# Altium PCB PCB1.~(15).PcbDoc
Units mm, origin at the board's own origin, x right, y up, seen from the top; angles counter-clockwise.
Board outline 145.29 x 144.91 mm, 2 copper layers (Top Layer, Bottom Layer); 48 components, 44 nets, 249 pads, 0 vias.
Unrouted connection lines stored in the file: 182.
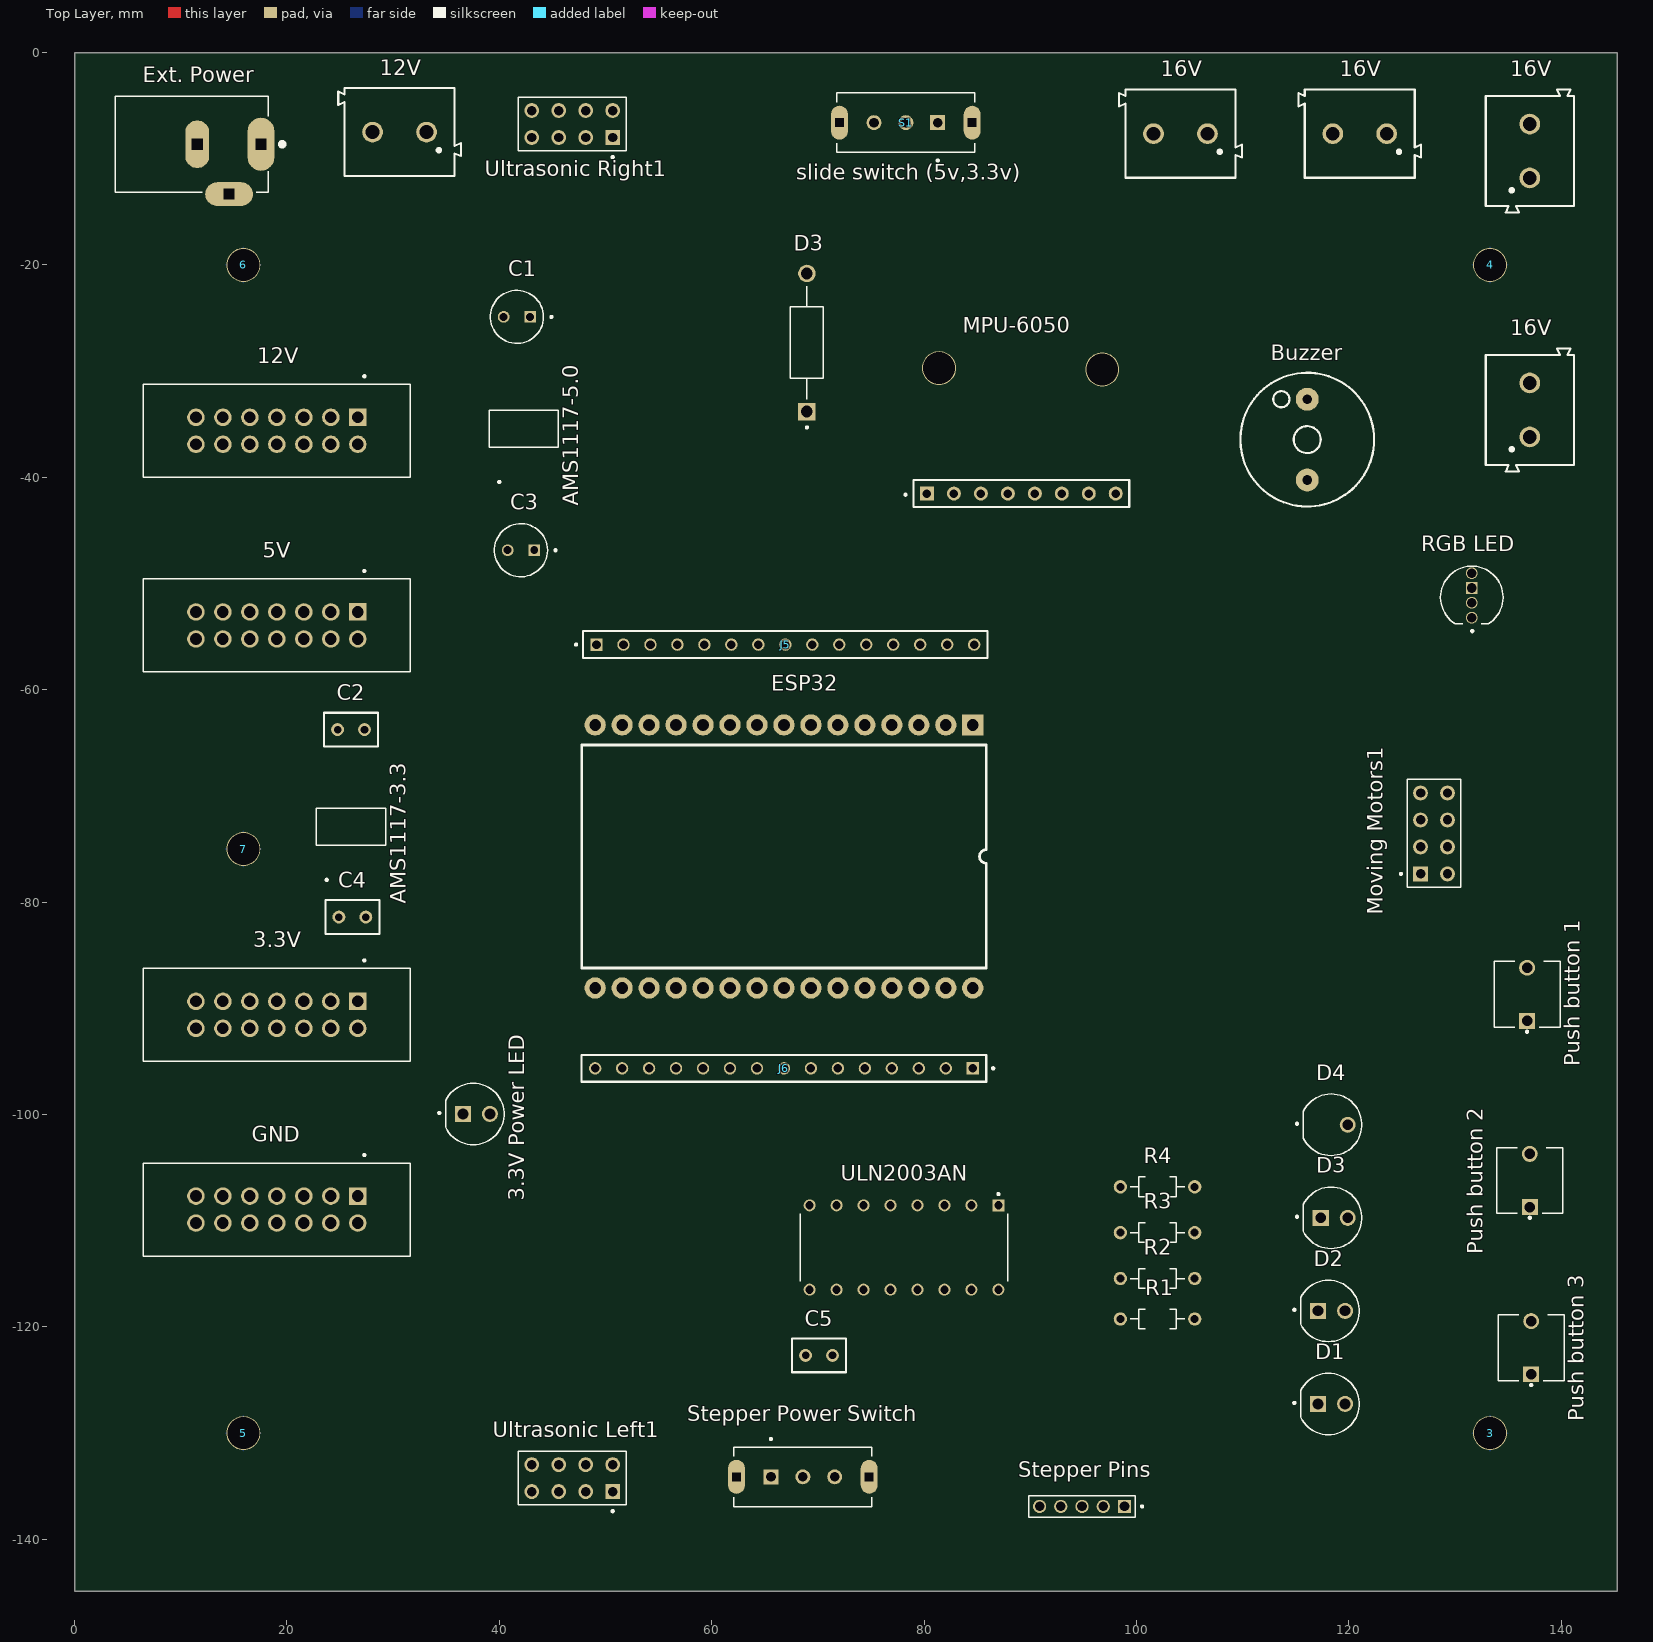
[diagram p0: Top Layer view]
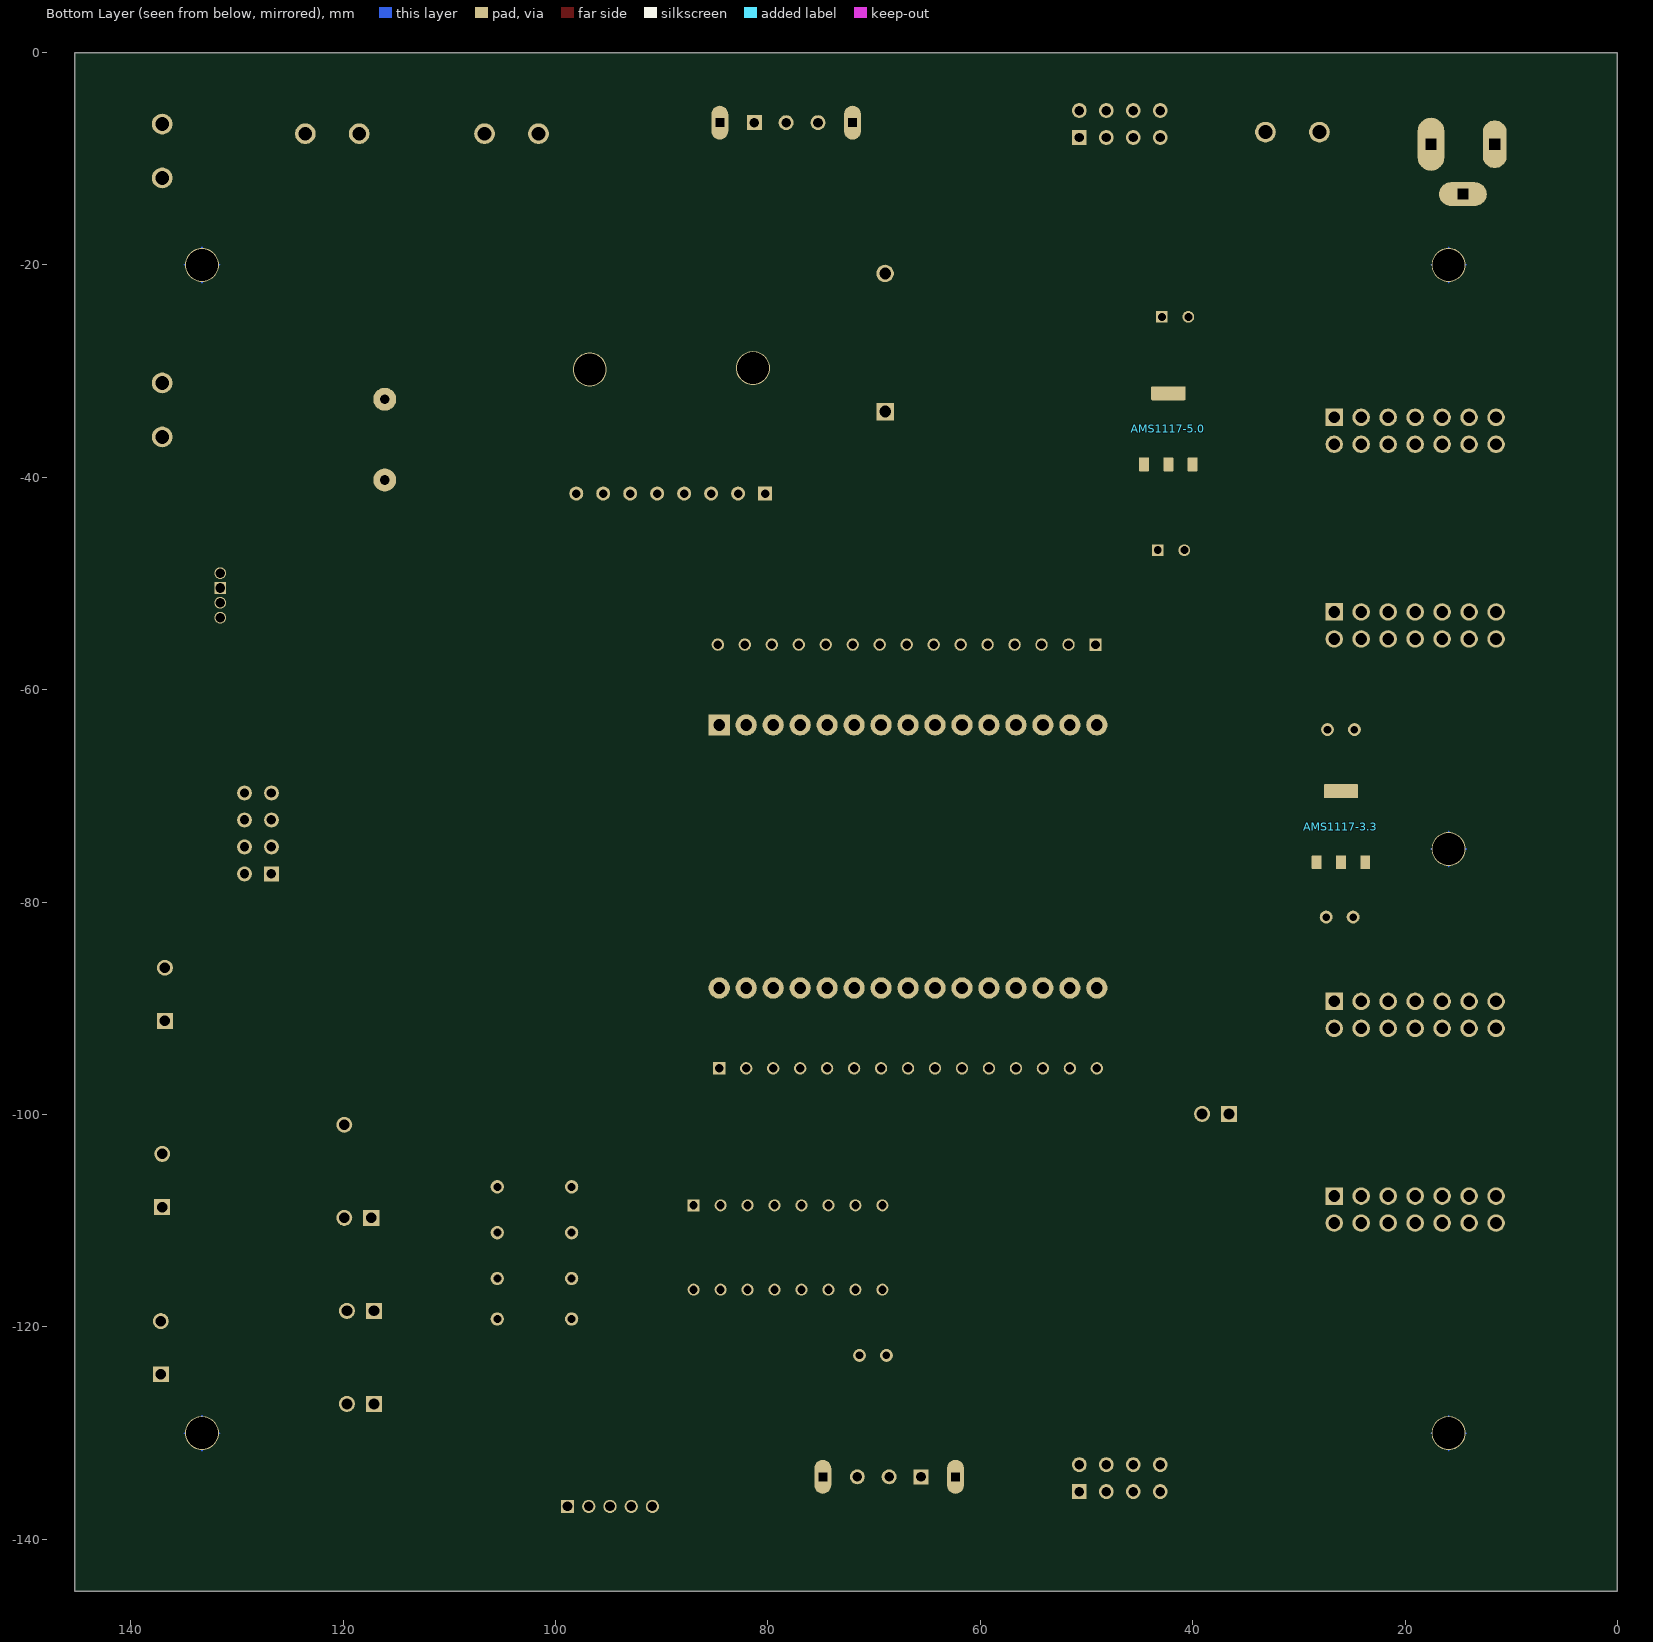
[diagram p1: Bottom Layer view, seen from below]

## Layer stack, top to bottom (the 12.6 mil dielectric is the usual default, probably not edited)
Top Solder: solder mask 0.0102, Solder Resist, Dk 3.5
Top Layer: signal copper 0.0356
Dielectric 1: dielectric 0.32, FR-4, Dk 4.8
Bottom Layer: signal copper 0.0356
Bottom Solder: solder mask 0.0102, Solder Resist, Dk 3.5

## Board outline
0,-144.907 145.288,-144.907 145.288,0 0,0

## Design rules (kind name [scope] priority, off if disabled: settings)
Clearance [All] p1: gap=0.254 ignorepadtopadclearanceinfootprint=FALSE except(0: Arc-Hole Track-Hole SMDPad-Hole THPad-Hole Via-Hole Fill-Hole Poly-Hole Region-Hole Text-Hole)
PolygonConnect [All] p1: connectstyle=Relief reliefconductorwidth=0.254 reliefentries=4 polygonreliefangle="90 Angle" airgapwidth=0.254
RoutingLayers [All] p1: top layer_v5=FALSE bottom layer_v5=TRUE
RoutingVias [All] p1: holewidth=0.711 width=1.27 viastyle="Through Hole" minholewidth=0.711 minwidth=1.27 maxholewidth=0.711 maxwidth=1.27
SolderMaskExpansion [All] p1: expansion=0.102 istentingtop=FALSE
Width [All] p1: maxlimit=0.5 minlimit=0.254 preferedwidth=0.5
29 further rules are at their usual default settings.

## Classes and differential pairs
component class Sheet1: 3 3.3V "3.3V Power LED" 4 5 5V 6 7 12V 16V AMS1117-3.3 AMS1117-5.0 Buzzer C1 C2 C3 C4 C5 D1 D2 D3 D4 ESP32 "Ext. Power" GND J5 J6 "Moving motors" "Moving Motors1" MPU-6050 "Push button 1" "Push button 2" "Push button 3" R1 R2 R3 R4 "RGB LED" S1 "Stepper Pins" "Stepper Power Switch" ULN2003AN "Ultrasonic Left1" "Ultrasonic Right1"

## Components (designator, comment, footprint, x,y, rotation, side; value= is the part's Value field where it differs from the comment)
3 "Mounting Hole" PCBComponent_1 133.288,-130 r90 top
3.3V "3.3v pin headers block" AMPHENOL_52601-S14-4LF 19.05,-90.616 r180 top
"3.3V Power LED" "LED 5mm" "LED 5mm"#1 37.846,-99.949 r0 top
4 "Mounting Hole" PCBComponent_1 133.288,-20 r90 top
5 "Mounting Hole" PCBComponent_1 15.9,-130 r90 top
5V "5v pin headers block" AMPHENOL_52601-S14-4LF 19.05,-53.949 r180 top
6 "Mounting Hole" PCBComponent_1 15.9,-20 r90 top
7 "Mounting Hole" PCBComponent_1 15.9,-75 r90 top
12V "12v pin headers block" AMPHENOL_52601-S14-4LF 19.05,-35.616 r180 top
12V "From Buck" 691213510002 30.607,-7.493 r180 top
16V "From Buck" 691213510002 137.033,-9.271 r90 top
16V "From Buck" 691213510002 137.033,-33.655 r90 top
16V "From Buck" 691213510002 121.02,-7.641 r180 top
16V "From Buck" 691213510002 104.14,-7.641 r180 top
AMS1117-3.3 "AMS1117-3.3" SOT229P700X180-4N 26.035,-72.898 r90 top
AMS1117-5.0 "AMS1117-5.0" SOT229P700X180-4N 42.291,-35.433 r90 top
Buzzer "WST-1205S" WST-1205S 116.078,-36.449 r90 top
C1 "CAP  33UF 50V RADIAL" "CAP  33UF 50V RADIAL" 41.656,-24.892 r180 top
C2 "Ceramic Capacitor 100nF" C320C 33.035,-56.754 r0 top
C3 "CAP  33UF 50V RADIAL" "CAP  33UF 50V RADIAL" 42.037,-46.863 r180 top
C4 "Ceramic Capacitor 100nF" C320C 33.162,-74.407 r0 top
C5 "Ceramic Capacitor 100nF" C320C 63.104,-129.682 r180 top
D1 "LED 5mm" "LED 5mm"#1 118.364,-127.254 r0 top
D2 "LED 5mm" "LED 5mm"#1 118.364,-118.491 r0 top
D3 "LED 5mm" "LED 5mm"#1 118.618,-109.728 r0 top
D3 "RL207" DIOAD1300W80L670D310 68.961,-27.305 r90 top
D4 "LED 5mm" "LED 5mm"#2 118.618,-100.965 r0 top
ESP32 "ESP32DEVKITV1" ESP32DEVKITV1 66.929,-75 r90 top
"Ext. Power" "DC Power Jack Female Socket" "DC Power Jack Female Socket" 17.557,-8.636 r180 top
GND "GND pin headers block" AMPHENOL_52601-S14-4LF 19.05,-108.949 r180 top
J5 "TS-115-T-A-1" SAMTEC_TS-115-T-A-1 66.929,-55.753 r0 top
J6 "TS-115-T-A-1" SAMTEC_TS-115-T-A-1 66.802,-95.649 r180 top
"Moving Motors1" "Pin header female block 8 pin" "Pin header female block 8 pin" 128.016,-73.533 r90 top (schematic designator "Moving motors1")
MPU-6050 "MPU-6050" MPU-6050 78.74,-43.053 r90 top
"Push button 1" "FSM8JRT" TE_FSM8JRT 136.779,-91.186 r90 top
"Push button 2" "FSM8JRT" TE_FSM8JRT 137.033,-108.712 r90 top
"Push button 3" "FSM8JRT" TE_FSM8JRT 137.16,-124.46 r90 top
R1 "Resistor" RESAD700W45L350D185 101.981,-119.253 r180 top
R2 "Resistor" RESAD700W45L350D185 101.981,-115.443 r180 top
R3 "Resistor" RESAD700W45L350D185 101.981,-111.125 r180 top
R4 "Resistor" RESAD700W45L350D185 101.981,-106.807 r180 top
"RGB LED" "common cathode" "LED RGB 5mm" 131.572,-51.308 r90 top
S1 "slide switch (5v,3.3v)" "Slide switch" 78.28,-6.604 r180 top
"Stepper Pins" "Pin hreader 5 pins" "Pin hreader 5 pins" 98.869,-136.906 r180 top
"Stepper Power Switch" "Slide switch" "Slide switch" 68.58,-134.112 r0 top
ULN2003AN "ULN2003AN" DIP794W45P254L1969H508Q16 78.105,-112.522 r270 top
"Ultrasonic Left1" "Pin header female block 8 pin" "Pin header female block 8 pin" 46.863,-134.239 r180 top
"Ultrasonic Right1" "Pin header female block 8 pin" "Pin header female block 8 pin" 46.863,-6.731 r180 top

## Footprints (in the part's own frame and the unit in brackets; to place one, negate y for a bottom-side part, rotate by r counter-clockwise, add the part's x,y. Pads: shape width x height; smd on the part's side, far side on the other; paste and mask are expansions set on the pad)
691213510002 [mm]
  round 1.95 hole 1.3: 1(-2.54,0) 2(2.54,0)
  silkscreen extent -5.78,-4.15 5.78,4.15, body extent -5.68,-3.94 5.68,4.16, height 10
AMPHENOL_52601-S14-4LF [mm]
  rect 1.65x1.65 hole 1.1: 1(-7.62,-1.27)
  round 1.65 hole 1.1: 2(-7.62,1.27) 3(-5.08,-1.27) 4(-5.08,1.27) 5(-2.54,-1.27) 6(-2.54,1.27) 7(0,-1.27) 8(0,1.27) 9(2.54,-1.27) 10(2.54,1.27) 11(5.08,-1.27) 12(5.08,1.27) 13(7.62,-1.27) 14(7.62,1.27)
  silkscreen extent -12.57,-5.23 12.57,4.38, body extent -12.57,-4.38 12.57,4.38, height 9.53
C320C [mm]
  round 1.21 hole 0.71: 1(-8.27,-7) 2(-5.73,-7)
  silkscreen extent -9.54,-8.59 -4.46,-5.41, body extent -9.53,-8.57 -4.45,-5.4, height 7.1
"CAP  33UF 50V RADIAL" [mm]
  round 1.1 hole 0.75: N(1.25,0)
  rect 1.1x1.1 hole 0.75: P(-1.25,0)
  silkscreen extent -3.35,-2.5 2.5,2.5, body extent -2.49,-2.5 2.5,2.5, height 11
"DC Power Jack Female Socket" [mm]
  oval 2.5x5 hole 1 square: 1(0,0)
  oval 2.25x4.5 hole 1 square: 2(6,0)
  oval 4.5x2.25 hole 1 square: 3(3,4.7)
  silkscreen extent -2.2,-4.5 13.7,4.5, body extent -0.7,-4.5 13.7,4.9, height 11
DIOAD1300W80L670D310 [mm]
  round 1.65 hole 1.1: A(6.5,0)
  rect 1.65x1.65 hole 1.1: C(-6.5,0)
  silkscreen extent -8.1,-1.55 5.32,1.55, body extent -6.9,-1.95 6.9,1.65, height 3.6
DIP794W45P254L1969H508Q16 [mm]
  rect 1.13x1.13 hole 0.78: 1(-3.97,8.89)
  round 1.13 hole 0.78: 2(-3.97,6.35) 3(-3.97,3.81) 4(-3.97,1.27) 5(-3.97,-1.27) 6(-3.97,-3.81) 7(-3.97,-6.35) 8(-3.97,-8.89) 9(3.97,-8.89) 10(3.97,-6.35) 11(3.97,-3.81) 12(3.97,-1.27) 13(3.97,1.27) 14(3.97,3.81) 15(3.97,6.35) 16(3.97,8.89)
  silkscreen extent -5.13,-9.77 3.18,9.77, body extent -3.95,-10.54 3.95,10.8, height 5.08
ESP32DEVKITV1 [mm]
  rect 2x2 hole 1.1: 1(11.684,-17.653)
  round 2 hole 1.1: 2(11.684,-15.113) 3(11.684,-12.573) 4(11.684,-10.033) 5(11.684,-7.493) 6(11.684,-4.953) 7(11.684,-2.413) 8(11.684,0.127) 9(11.684,2.667) 10(11.684,5.207) 11(11.684,7.747) 12(11.684,10.287) 13(11.684,12.827) 14(11.684,15.367) 15(11.684,17.907) 16(-13.086,17.907) 17(-13.086,15.367) 18(-13.086,12.827) 19(-13.086,10.287) 20(-13.086,7.747) 21(-13.086,5.207) 22(-13.086,2.667) 23(-13.086,0.127) 24(-13.086,-2.413) 25(-13.086,-4.953) 26(-13.086,-7.493) 27(-13.086,-10.033) 28(-13.086,-12.573) 29(-13.086,-15.113) 30(-13.086,-17.653)
  silkscreen extent -11.2,-18.92 9.79,19.18, body extent -15.13,-28.49 13.86,24.48, height 8.36
"LED 5mm"#1 [mm]
  round 1.508 hole 1: A(1.27,0)
  rect 1.508x1.508 hole 1: C(-1.27,0)
  silkscreen extent -3.6,-2.9 2.6,2.9, body extent -2.88,-2.9 2.51,2.9, height 12.1
"LED 5mm"#2 [mm]
  round 1.508 hole 1: A(1.27,0)
  rect 1.508x1.508 on Top Overlay: C(-1.27,0)
  silkscreen extent -3.6,-2.9 2.6,2.9, body extent -2.88,-2.9 2.51,2.9, height 12.1
"LED RGB 5mm" [mm]
  round 1.1 hole 0.9: 1(-1.905,0) 2(-0.508,0) 4(2.286,0)
  rect 1.1x1.1 hole 0.9: 3(0.889,0)
  silkscreen extent -3.27,-2.95 2.95,2.95, body extent -2.47,-3.05 2.98,2.84, height 9.6
MPU-6050 [mil]
  rect 52x52 hole 32: 01(60,-60)
  round 52 hole 32: 02(60,-160) 03(60,-260) 04(60,-360) 05(60,-460) 06(60,-560) 07(60,-660) 08(60,-760)
  round 125.98 hole 118.11: ""(520,-710) ""(525,-105)
  silkscreen extent 10,-810 110,23, body extent 15,-811 615,-9, height 612
PCBComponent_1 [mm]
  round 3.2 hole 3: ""(0,0)
  Bottom Layer lines w0.15: 0,1.649 0,-1.651 ; -1.651,0 1.649,0
"Pin header female block 8 pin" [mm]
  rect 1.398x1.398 hole 0.89: 1(-3.81,1.27)
  round 1.398 hole 0.89: 2(-1.27,1.27) 3(1.27,1.27) 4(3.81,1.27) 5(-3.81,-1.27) 6(-1.27,-1.27) 7(1.27,-1.27) 8(3.81,-1.27)
  silkscreen extent -5.08,-2.51 5.08,3.21, body extent -5.08,-2.51 5.08,2.51, height 6.22
"Pin hreader 5 pins" [mm]
  rect 1.25x1.25 hole 0.9: 1(0,0)
  round 1.25 hole 0.9: 2(2,0) 3(4,0) 4(6,0) 5(8,0)
  silkscreen extent -1.75,-1 9,1, body extent -1,-1 9,1, height 5.65
RESAD700W45L350D185 [mm]
  round 1.258 hole 0.75: 1(-3.5,0) 2(3.5,0)
  silkscreen extent -2.55,-0.92 2.55,0.92, body extent -3.72,-1.05 3.72,0.8, height 1.85
SAMTEC_TS-115-T-A-1 [mil]
  rect 45.78x45.78 hole 32: 01(-700,0)
  round 45.78 hole 32: 02(-600,0) 03(-500,0) 04(-400,0) 05(-300,0) 06(-200,0) 07(-100,0) 08(0,0) 09(100,0) 10(200,0) 11(300,0) 12(400,0) 13(500,0) 14(600,0) 15(700,0)
  silkscreen extent -780,-50 750,50, body extent -754,-50 754,50, height 326
"Slide switch" [mm]
  rect 1.408x1.408 hole 0.9: 1(-3,0)
  round 1.408 hole 0.9: 2(0,0) 3(3,0)
  oval 1.6x3.2 hole 0.8 square: SH1(-6.25,0) SH2(6.25,0)
  silkscreen extent -6.5,-2.8 6.5,3.66, body extent -6.5,-5.8 6.5,2.8, height 6
SOT229P700X180-4N [mm]
  rrect15% 1.31x0.93 smd far side: 1(-3.345,2.29) 2(-3.345,0) 3(-3.345,-2.29)
  rrect15% 1.31x3.24 smd far side: 4(3.345,0)
  silkscreen extent -5.1,-3.25 1.75,3.25, body extent -3.5,-3.25 3.5,3.25, height 1.8
TE_FSM8JRT [mil]
  rect 59x59 hole 39: 1(0,0)
  round 59 hole 39: 2(197,0)
  silkscreen extent -44,-122 220,122, body extent -22,-122 222,122, height 372
WST-1205S [mil]
  round 85 hole 36: NEG(-149.61,0) POS(149.61,0)
  silkscreen extent -248,-248 248,248, body extent -236,-236 236,236, height 394

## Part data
3.3V 5V 12V GND: library part 52601-S14-4LF, Package=None
"3.3V Power LED" D1 D2 D3 D4: "Red 623nm LED Indication - Discrete 1.9V Radial", Package=None
12V 16V 16V 16V 16V: library part "Terminal Block", "2 Position Wire to Board Terminal Block Horizontal with Board 0.200 (5.08mm) Through Hole", Package=None
AMS1117-3.3 AMS1117-5.0 J5 J6 "Moving Motors1" "Stepper Pins" "Stepper Power Switch" ULN2003AN "Ultrasonic Left1" "Ultrasonic Right1": Package=None
Buzzer: "BUZZER 2.3KHZ 4-6VDC", Package=None
C1 C3: "NHG-A", Package=None
C2 C4 C5: "0.1ÂµF Â±20% 50V Ceramic Capacitor Z5U Radial", Package="Radial KEMET"
D3: "Semiconductors and Actives, Power Diodes, Discretes (diodes, transistors, thyristors ...), Diodes", Package=None
"Ext. Power": "2.0 mm Center Pin, 2.5 A, Right Angle, Through Hole, Dc Power Jack Connector", Package=None
"Push button 1" "Push button 2" "Push button 3": "Tactile Switches PUSHBUTTON SWITCH TACT", Package=None
R1 R2 R3 R4: "CFR16 5% 10K", Package=None
"RGB LED": library part "LED RGB 5mm", Package=None
S1: library part "Slide switch", Package=None

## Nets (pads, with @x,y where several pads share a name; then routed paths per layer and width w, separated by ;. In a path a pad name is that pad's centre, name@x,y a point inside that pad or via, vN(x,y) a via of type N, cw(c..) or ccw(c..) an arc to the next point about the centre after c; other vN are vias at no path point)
3.3V: 3.3V.1 3.3V.2 3.3V.3 3.3V.4 3.3V.5 3.3V.6 3.3V.7 3.3V.8 3.3V.9 3.3V.10 3.3V.11 3.3V.12 3.3V.13 3.3V.14 AMS1117-3.3.2 C2.2 ESP32.1 J5.15 MPU-6050.01
+5: 5V.1 5V.2 5V.3 5V.4 5V.5 5V.6 5V.7 5V.8 5V.9 5V.10 5V.11 5V.12 5V.13 5V.14 "Stepper Power Switch.3" "Ultrasonic Left1.1" "Ultrasonic Left1.5" "Ultrasonic Right1.1" "Ultrasonic Right1.5" AMS1117-5.0.2 C1.P S1.1 S1.2
+12: 12V.1 12V.2@26.67,-36.886 12V.3 12V.4 12V.5 12V.6 12V.7 12V.8 12V.9 12V.10 12V.11 12V.12 12V.13 12V.14 "Ext. Power.1" "Stepper Power Switch.1" D3.A@68.961,-20.805
GND: 12V.2@28.067,-7.493 "3.3V Power LED.C" "Ext. Power.2" "Ext. Power.3" "Push button 1.2" "Push button 2.2" "Push button 3.2" "RGB LED.3" "Ultrasonic Left1.4" "Ultrasonic Left1.7" "Ultrasonic Left1.8" "Ultrasonic Right1.4" "Ultrasonic Right1.7" "Ultrasonic Right1.8" AMS1117-3.3.1 AMS1117-5.0.1 Buzzer.NEG C1.N C2.1 C3.N C4.1 C5.1 ESP32.2 ESP32.29 GND.1 GND.2 GND.3 GND.4 GND.5 GND.6 GND.7 GND.8 GND.9 GND.10 GND.11 GND.12 GND.13 GND.14 J5.14 J6.02 MPU-6050.02 ULN2003AN.8 ULN2003AN.10 ULN2003AN.11 ULN2003AN.12
"Net3.3V Power LED_A": "3.3V Power LED.A" AMS1117-3.3.3 C4.2 S1.3
Net16V_1: 16V.1
Net16V_2: 16V.2
NetAMS1117-5.0_3: AMS1117-5.0.3 C3.P D3.C@68.961,-33.805
NetBuzzer_POS: Buzzer.POS ESP32.15 J5.01
NetC5_2: "Stepper Pins.1" "Stepper Power Switch.2" C5.2 D1.A D2.A D3.A@119.888,-109.728 D4.A ULN2003AN.9
NetD1_C: D1.C R1.1
NetD2_C: D2.C R2.1
NetD3_C: D3.C@117.348,-109.728 R3.1
NetD4_C: R4.1
NetESP32_3: ESP32.3 J5.13 ULN2003AN.4
NetESP32_4: "RGB LED.2" ESP32.4 J5.12
NetESP32_5: "Moving Motors1.8" ESP32.5 J5.11
NetESP32_6: "Moving Motors1.7" ESP32.6 J5.10
NetESP32_7: "Moving Motors1.6" ESP32.7 J5.09
NetESP32_8: "Ultrasonic Right1.6" ESP32.8 J5.08
NetESP32_9: "Ultrasonic Right1.3" ESP32.9 J5.07
NetESP32_10: "Ultrasonic Right1.2" ESP32.10 J5.06
NetESP32_11: ESP32.11 J5.05 MPU-6050.04
NetESP32_12: "RGB LED.4" ESP32.12 J5.04
NetESP32_13: "RGB LED.1" ESP32.13 J5.03
NetESP32_14: ESP32.14 J5.02 MPU-6050.03
NetESP32_16: ESP32.16 J6.15
NetESP32_17: "Push button 1.1" ESP32.17 J6.14
NetESP32_18: "Push button 2.1" ESP32.18 J6.13
NetESP32_19: "Push button 3.1" ESP32.19 J6.12
NetESP32_20: "Ultrasonic Left1.3" ESP32.20 J6.11
NetESP32_21: "Ultrasonic Left1.2" ESP32.21 J6.10
NetESP32_22: "Ultrasonic Left1.6" ESP32.22 J6.09
NetESP32_23: "Moving Motors1.1" ESP32.23 J6.08
NetESP32_24: "Moving Motors1.3" ESP32.24 J6.07
NetESP32_25: "Moving Motors1.2" ESP32.25 J6.06
NetESP32_26: ESP32.26 J6.05 ULN2003AN.1
NetESP32_27: ESP32.27 J6.04 ULN2003AN.2
NetESP32_28: ESP32.28 J6.03 ULN2003AN.3
NetESP32_30: ESP32.30 J6.01
NetR1_2: "Stepper Pins.2" R1.2 ULN2003AN.16
NetR2_2: "Stepper Pins.3" R2.2 ULN2003AN.15
NetR3_2: "Stepper Pins.4" R3.2 ULN2003AN.14
NetR4_2: "Stepper Pins.5" R4.2 ULN2003AN.13
pads on no net: 3. 4. 5. 6. 7. "Moving Motors1.4" "Moving Motors1.5" "Stepper Power Switch.SH1" "Stepper Power Switch.SH2" AMS1117-3.3.4 AMS1117-5.0.4 D4.C MPU-6050. MPU-6050.05 MPU-6050.06 MPU-6050.07 MPU-6050.08 S1.SH1 S1.SH2 ULN2003AN.5 ULN2003AN.6 ULN2003AN.7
